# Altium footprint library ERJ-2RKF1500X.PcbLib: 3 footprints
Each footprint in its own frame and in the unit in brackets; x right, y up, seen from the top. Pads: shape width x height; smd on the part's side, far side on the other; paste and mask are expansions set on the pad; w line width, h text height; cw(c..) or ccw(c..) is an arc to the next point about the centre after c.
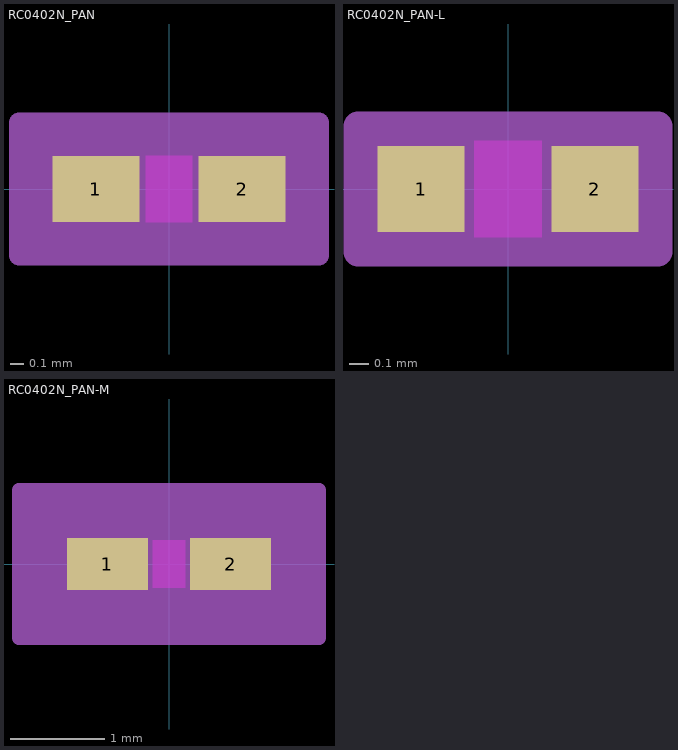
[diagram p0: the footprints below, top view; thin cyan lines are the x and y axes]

## RC0402N_PAN [mm]
pads (2):
  rect 0.656x0.5 smd paste+0 mask+0: 1(-0.553,0) 2(0.553,0)
Top Layer keep-out:
  region: -0.174,-0.199 -0.174,0.199 0.174,0.199 0.174,-0.199
Top Overlay:
  text ".Designator" at -3.492,-0.635 h1.27
Keep-Out Layer:
  region: -0.174,-0.25 -0.174,0.25 0.174,0.25 0.174,-0.25
Mechanical 13:
  lines w0.025: -0.525,-0.25 -0.525,0.25 ; -0.525,-0.25 -0.225,-0.25 -0.225,0.25 -0.525,0.25 ; -0.525,-0.25 0.525,-0.25 ; -0.525,-0.25 -0.525,0.25 ; -0.525,0.25 0.525,0.25 ; 0.525,-0.25 0.225,-0.25 0.225,0.25 0.525,0.25 ; 0.525,-0.25 0.525,0.25 ; 0.525,-0.25 0.525,0.25
  text ".Designator" at -3.492,-0.635 h1.27
Mechanical 15:
  region: 1.135,-0.504 -1.135,-0.504 -1.135,0.504 1.135,0.504
  lines w0.152: -1.135,-0.504 -1.135,0.504 1.135,0.504 1.135,-0.504 -1.135,-0.504
3D body "RC0402N_PAN.step": height 0.71, standoff 0, extent -0.525,-0.25 0.525,0.25

## RC0402N_PAN-L [mm]
pads (2):
  rect 0.452x0.449 smd paste+0 mask+0: 1(-0.451,0) 2(0.451,0)
Top Layer keep-out:
  region: -0.174,-0.199 -0.174,0.199 0.174,0.199 0.174,-0.199
Top Overlay:
  text ".Designator" at -3.492,-0.635 h1.27
Keep-Out Layer:
  region: -0.174,-0.25 -0.174,0.25 0.174,0.25 0.174,-0.25
Mechanical 13:
  lines w0.025: -0.525,-0.25 -0.525,0.25 ; -0.525,-0.25 -0.225,-0.25 -0.225,0.25 -0.525,0.25 ; -0.525,-0.25 0.525,-0.25 ; -0.525,-0.25 -0.525,0.25 ; -0.525,0.25 0.525,0.25 ; 0.525,-0.25 0.225,-0.25 0.225,0.25 0.525,0.25 ; 0.525,-0.25 0.525,0.25 ; 0.525,-0.25 0.525,0.25
  text ".Designator" at -3.492,-0.635 h1.27
Mechanical 15:
  region: 0.779,-0.326 -0.779,-0.326 -0.779,0.326 0.779,0.326
  lines w0.152: -0.779,-0.326 -0.779,0.326 0.779,0.326 0.779,-0.326 -0.779,-0.326
3D body "RC0402N_PAN.step": height 0.71, standoff 0, extent -0.525,-0.25 0.525,0.25

## RC0402N_PAN-M [mm]
pads (2):
  rect 0.859x0.551 smd paste+0 mask+0: 1(-0.654,0) 2(0.654,0)
Top Layer keep-out:
  region: -0.174,-0.199 -0.174,0.199 0.174,0.199 0.174,-0.199
Top Overlay:
  text ".Designator" at -3.492,-0.635 h1.27
Keep-Out Layer:
  region: -0.174,-0.25 -0.174,0.25 0.174,0.25 0.174,-0.25
Mechanical 13:
  lines w0.025: -0.525,-0.25 -0.525,0.25 ; -0.525,-0.25 -0.225,-0.25 -0.225,0.25 -0.525,0.25 ; -0.525,-0.25 0.525,-0.25 ; -0.525,-0.25 -0.525,0.25 ; -0.525,0.25 0.525,0.25 ; 0.525,-0.25 0.225,-0.25 0.225,0.25 0.525,0.25 ; 0.525,-0.25 0.525,0.25 ; 0.525,-0.25 0.525,0.25
  text ".Designator" at -3.492,-0.635 h1.27
Mechanical 15:
  region: 1.592,-0.783 -1.592,-0.783 -1.592,0.783 1.592,0.783
  lines w0.152: -1.592,-0.783 -1.592,0.783 1.592,0.783 1.592,-0.783 -1.592,-0.783
3D body "RC0402N_PAN.step": height 0.71, standoff 0, extent -0.525,-0.25 0.525,0.25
